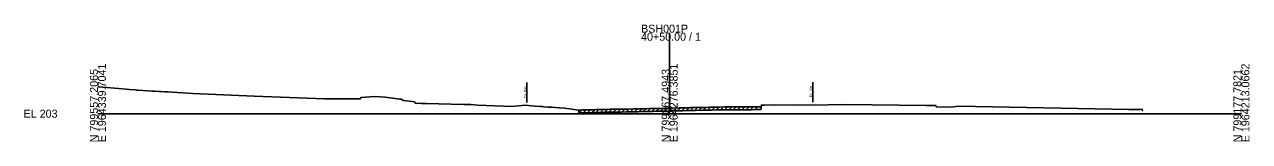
# Model space of a CAD drawing. Extents: x -26 to 1403, y -10 to 19587.
# Drawn here: x 974.3 to 1402.8, y 4490.3 to 4531.1 of the extents above; entities that cross this region are included whole.
import ezdxf

# ---------------------------------------------------------------- set-up
doc = ezdxf.new("R2010")
doc.units = 0
for name, color, linetype in [('Default', 7, 'Continuous'), ('RD_GPK_XS_Cell', 7, 'Continuous'), ('RD_XS_ExGround', 7, 'Continuous'), ('RD_XS_ExPaveRet', 7, 'Continuous'), ('RD_XS_ExRW', 7, 'Continuous'), ('RD_XS_TX_Elev_EX', 7, 'Continuous')]:
    doc.layers.add(name, color=color, linetype=linetype)

msp = doc.modelspace()

# ---------------------------------------------------------------- linework, layer by layer
at = {"layer": 'RD_GPK_XS_Cell'}
for p, q in [((1200, 4500), (1200, 4528.26)), ((1000, 4500), (1200, 4500)), ((1200, 4500), (1400, 4500))]:
    msp.add_line(p, q, dxfattribs=at)
at = {"layer": 'RD_XS_ExGround'}
msp.add_lwpolyline([(1000, 4509.42), (1000.39, 4509.39), (1001.75, 4509.27), (1007.21, 4508.82), (1009.91, 4508.57), (1010.93, 4508.47), (1013.02, 4508.3), (1013.64, 4508.26), (1014.05, 4508.23), (1017.51, 4508), (1018.94, 4507.9), (1019.85, 4507.84), (1021.42, 4507.73), (1021.91, 4507.7), (1023.36, 4507.6), (1024.39, 4507.63), (1033.24, 4507.05), (1049.26, 4506.37), (1054.6, 4506.13), (1079.25, 4505.13), (1080.25, 4505.14), (1083.2, 4505.17), (1091.87, 4505.23), (1091.98, 4505.68), (1095.25, 4505.82), (1096.92, 4505.95), (1100.52, 4505.73), (1104.8, 4505.13), (1105.46, 4505.1), (1106.1, 4505.06), (1106.93, 4504.6), (1110.86, 4504.09), (1111, 4503.64), (1113.16, 4503.58), (1113.8, 4503.59), (1114.87, 4503.57), (1128.05, 4503.19), (1130.43, 4503.16), (1132.9, 4502.97), (1144.82, 4502.54), (1149.43, 4502.93), (1152.85, 4502.64), (1154.8, 4502.47), (1155.51, 4502.45), (1155.98, 4502.42), (1157.43, 4502.32), (1158.67, 4502.24), (1161.38, 4502.09), (1163.31, 4501.93), (1163.97, 4501.81), (1165.07, 4501.64), (1166.57, 4501.42), (1167.31, 4501.35), (1168.13, 4501.28), (1168.68, 4501.28), (1169.22, 4501.28), (1169.63, 4501.29), (1171.28, 4501.32), (1171.85, 4501.33), (1173.26, 4501.38), (1174.49, 4501.41), (1177.47, 4501.49), (1179.18, 4501.53), (1179.75, 4501.54), (1180.85, 4501.56), (1181.16, 4501.57), (1181.93, 4501.57), (1182.37, 4501.57), (1183.12, 4501.58), (1185.34, 4501.61), (1187.63, 4501.66), (1189.03, 4501.68), (1190.26, 4501.7), (1191, 4501.72), (1192.97, 4501.77), (1193.56, 4501.79), (1194.1, 4501.8), (1195.54, 4501.83), (1196.93, 4501.85), (1198.17, 4501.87), (1198.93, 4501.88), (1200, 4501.9), (1201.13, 4501.92), (1203.48, 4501.99), (1204.65, 4502.02), (1206.11, 4502.07), (1207.28, 4502.1), (1208.74, 4502.14), (1209.06, 4502.15), (1211.38, 4502.18), (1212.78, 4502.21), (1214.02, 4502.24), (1214.75, 4502.26), (1216.64, 4502.31), (1216.95, 4502.31), (1217.47, 4502.32), (1219.23, 4502.37), (1219.78, 4502.37), (1221.89, 4502.37), (1224.81, 4502.38), (1226.56, 4502.39), (1227.14, 4502.39), (1228.54, 4502.39), (1229.79, 4502.41), (1230.23, 4502.42), (1230.99, 4502.42), (1231.92, 4502.41), (1232.01, 4502.54), (1232.11, 4502.99), (1233.13, 4503.01), (1237.09, 4503.14), (1245.36, 4502.97), (1247.56, 4503.07), (1249.53, 4503.02), (1261.4, 4503.17), (1289.68, 4502.84), (1292.55, 4502.81), (1293.15, 4502.81), (1293.25, 4502.35), (1298.45, 4502.25), (1301.07, 4502.65), (1360.63, 4501.48), (1361.27, 4501.49), (1362.18, 4501.49), (1363.09, 4501.49), (1364.12, 4501.49), (1364.55, 4501.5), (1365.29, 4501.52), (1365.4, 4501.07), (1365.5, 4501.06)], dxfattribs=at)
at = {"layer": 'RD_XS_ExPaveRet'}
for p, q in [((1168.25, 4500.28), (1169.25, 4501.28)), ((1168.25, 4500.28), (1168.25, 4501.28)), ((1168.25, 4500.28), (1168.68, 4500.28)), ((1168.68, 4500.28), (1169.22, 4500.28)), ((1169.22, 4500.28), (1169.63, 4500.29)), ((1169.63, 4500.29), (1171.28, 4500.32)), ((1169.75, 4500.29), (1170.77, 4501.31)), ((1171.25, 4500.32), (1172.28, 4501.35)), ((1171.28, 4500.32), (1171.85, 4500.33)), ((1171.85, 4500.33), (1173.26, 4500.38)), ((1172.75, 4500.36), (1173.78, 4501.39)), ((1173.26, 4500.38), (1174.49, 4500.41)), ((1174.25, 4500.4), (1175.28, 4501.43)), ((1174.49, 4500.41), (1177.47, 4500.49)), ((1175.75, 4500.44), (1176.78, 4501.47)), ((1177.25, 4500.48), (1178.28, 4501.5)), ((1177.47, 4500.49), (1179.18, 4500.53)), ((1178.75, 4500.52), (1179.78, 4501.54)), ((1179.18, 4500.53), (1179.75, 4500.54)), ((1179.75, 4500.54), (1180.85, 4500.56)), ((1180.25, 4500.55), (1181.27, 4501.57)), ((1180.85, 4500.56), (1181.16, 4500.57)), ((1181.16, 4500.57), (1181.93, 4500.57)), ((1181.75, 4500.57), (1182.76, 4501.58)), ((1181.93, 4500.57), (1182.37, 4500.57)), ((1182.37, 4500.57), (1183.12, 4500.58)), ((1183.12, 4500.58), (1185.34, 4500.61)), ((1183.25, 4500.58), (1184.27, 4501.6)), ((1184.75, 4500.6), (1185.77, 4501.62)), ((1185.34, 4500.61), (1187.63, 4500.66)), ((1186.25, 4500.63), (1187.27, 4501.65)), ((1187.63, 4500.66), (1189.03, 4500.68)), ((1187.75, 4500.66), (1188.77, 4501.68)), ((1189.03, 4500.68), (1190.26, 4500.7)), ((1189.25, 4500.69), (1190.27, 4501.71)), ((1190.26, 4500.7), (1191, 4500.72)), ((1190.75, 4500.72), (1191.78, 4501.74)), ((1191, 4500.72), (1192.97, 4500.77)), ((1192.25, 4500.75), (1193.28, 4501.78)), ((1192.97, 4500.77), (1193.56, 4500.79)), ((1193.56, 4500.79), (1194.1, 4500.8)), ((1193.75, 4500.79), (1194.77, 4501.81)), ((1194.1, 4500.8), (1195.54, 4500.83)), ((1195.25, 4500.82), (1196.27, 4501.84)), ((1195.54, 4500.83), (1196.93, 4500.85)), ((1196.75, 4500.85), (1197.77, 4501.87)), ((1196.93, 4500.85), (1198.17, 4500.87)), ((1198.17, 4500.87), (1198.93, 4500.88)), ((1198.25, 4500.87), (1199.27, 4501.89)), ((1198.93, 4500.88), (1200, 4500.9)), ((1199.75, 4500.9), (1200.77, 4501.92)), ((1200, 4500.9), (1201.13, 4500.92)), ((1201.13, 4500.92), (1203.48, 4500.99)), ((1201.25, 4500.93), (1202.28, 4501.96)), ((1202.75, 4500.97), (1203.78, 4502)), ((1203.48, 4500.99), (1204.65, 4501.02)), ((1204.25, 4501.01), (1205.29, 4502.04)), ((1204.65, 4501.02), (1206.11, 4501.07)), ((1205.75, 4501.06), (1206.79, 4502.09)), ((1206.11, 4501.07), (1207.28, 4501.1)), ((1207.25, 4501.1), (1208.28, 4502.13)), ((1207.28, 4501.1), (1208.74, 4501.14)), ((1208.74, 4501.14), (1209.06, 4501.15)), ((1208.75, 4501.14), (1209.77, 4502.16)), ((1209.06, 4501.15), (1211.38, 4501.18)), ((1210.25, 4501.16), (1211.27, 4502.18)), ((1211.38, 4501.18), (1212.78, 4501.21)), ((1211.75, 4501.19), (1212.77, 4502.21)), ((1212.78, 4501.21), (1214.02, 4501.24)), ((1213.25, 4501.22), (1214.28, 4502.24)), ((1214.02, 4501.24), (1214.75, 4501.26)), ((1214.75, 4501.26), (1215.78, 4502.28)), ((1214.75, 4501.26), (1216.64, 4501.31)), ((1216.25, 4501.3), (1217.28, 4502.32)), ((1216.64, 4501.31), (1216.95, 4501.31)), ((1216.95, 4501.31), (1217.47, 4501.32)), ((1217.47, 4501.32), (1219.23, 4501.37)), ((1217.75, 4501.33), (1218.78, 4502.36)), ((1219.23, 4501.37), (1219.78, 4501.37)), ((1219.25, 4501.37), (1220.25, 4502.37)), ((1219.78, 4501.37), (1221.89, 4501.37)), ((1220.75, 4501.37), (1221.75, 4502.37)), ((1221.89, 4501.37), (1224.81, 4501.38)), ((1222.25, 4501.37), (1223.26, 4502.37)), ((1223.75, 4501.38), (1224.76, 4502.38)), ((1224.81, 4501.38), (1226.56, 4501.39)), ((1225.25, 4501.38), (1226.26, 4502.38)), ((1226.56, 4501.39), (1227.14, 4501.39)), ((1226.75, 4501.39), (1227.76, 4502.39)), ((1227.14, 4501.39), (1228.54, 4501.39)), ((1228.25, 4501.39), (1229.26, 4502.4)), ((1228.54, 4501.39), (1229.79, 4501.41)), ((1229.75, 4501.41), (1230.76, 4502.42)), ((1229.79, 4501.41), (1230.23, 4501.42)), ((1230.23, 4501.42), (1230.99, 4501.42)), ((1230.99, 4501.42), (1231.92, 4501.41)), ((1231.92, 4501.41), (1232.01, 4501.68)), ((1232.01, 4502.68), (1232.01, 4501.68))]:
    msp.add_line(p, q, dxfattribs=at)
at = {"layer": 'RD_XS_ExRW'}
for p, q in [((1150.03, 4503.88), (1150.03, 4510.88)), ((1250.03, 4504.02), (1250.03, 4511.02))]:
    msp.add_line(p, q, dxfattribs=at)

# ---------------------------------------------------------------- texts
at = {"layer": 'Default'}
msp.add_text('-', height=0.0001, dxfattribs=at).set_placement((1000, 4500))
at = {"layer": 'RD_GPK_XS_Cell'}
for s, p in [('BSH001P', (1190, 4528.26)), ('40+50.00 / 1', (1190, 4525.46)), ('EL 203', (974, 4498.6))]:
    msp.add_text(s, height=2.8, dxfattribs=at).set_placement(p)
for s, p in [('E 1964339.7041', (1002.8, 4490)), ('E 1964276.3851', (1202.8, 4490)), ('E 1964213.0662', (1402.8, 4490)), ('N 799557.2065', (1000, 4490)), ('N 799367.4943', (1200, 4490)), ('N 799177.7821', (1400, 4490))]:
    msp.add_text(s, height=2.8, rotation=90, dxfattribs=at).set_placement(p)
at = {"layer": 'RD_XS_ExRW'}
for p in [(1149.78, 4505.55), (1249.78, 4505.7)]:
    msp.add_text('EX. R/W ', height=0.75, rotation=90, dxfattribs=at).set_placement(p)
at = {"layer": 'RD_XS_TX_Elev_EX'}
msp.add_text('204.90', height=1, dxfattribs=at).set_placement((1197.95, 4499.4))

doc.saveas('drawing.dxf')
